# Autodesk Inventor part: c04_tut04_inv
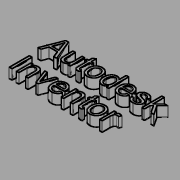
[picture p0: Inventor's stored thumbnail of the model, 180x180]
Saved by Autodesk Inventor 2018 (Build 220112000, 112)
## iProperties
Created: 2017-04
Part Number: c04_tut04_inv
Material: Generic
Document SubType Name: Modeling
Designer: CADCIM 00
Density: 1 g/cm^3
Appearance: Default
Author: CADCIM 00
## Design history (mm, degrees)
sketch "Sketch1"
  geometry: L1 (0.506, 21.792)-(30.182, 21.792); L2 (30.182, 21.792)-(30.182, 9.249); L3 (30.182, 9.249)-(0.506, 9.249); L4 (0.506, 9.249)-(0.506, 21.792); 1 further point
  constraints: 2 other
extrude "Extrusion1" new body sketch "Sketch1" distance "d0" = 2.5; taper "d1" = 0 deg
body "Solid1"
